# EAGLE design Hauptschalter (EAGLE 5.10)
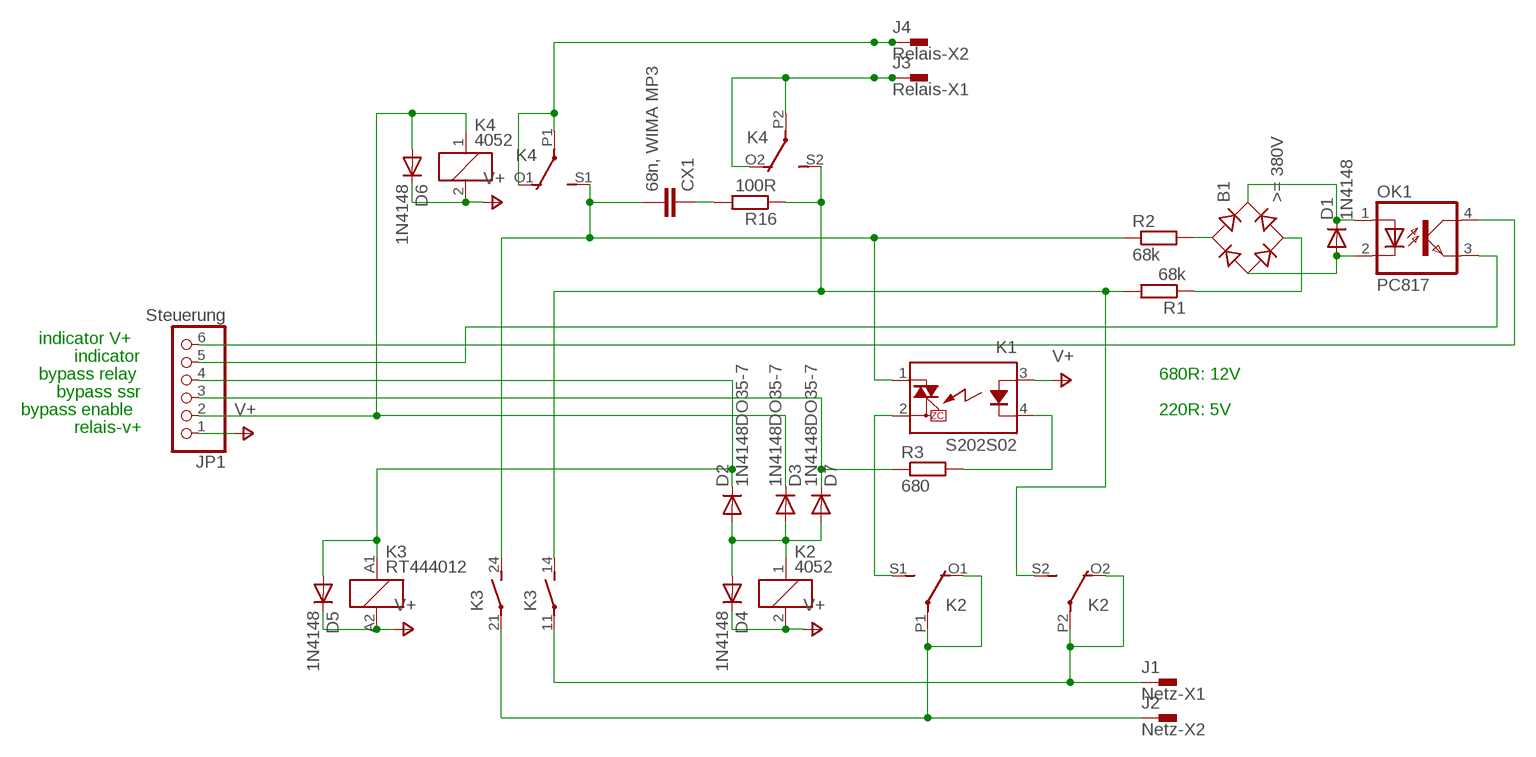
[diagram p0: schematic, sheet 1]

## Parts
B1  >= 380V  B-DIL  [B-DIL]
CX1  68n, WIMA MP3  CXXC15B8  [XC15B8]
D1  1N4148  DIODE-MINIMELF  [MINIMELF]
D2  1N4148DO35-7  [DO35-7]
D3  1N4148DO35-7  [DO35-7]
D4  1N4148  DIODE-MINIMELF  [MINIMELF]
D5  1N4148  DIODE-MINIMELF  [MINIMELF]
D6  1N4148  DIODE-MINIMELF  [MINIMELF]
D7  1N4148DO35-7  [DO35-7]
J1  Netz-X1  PIN2F061.080  [F061.080]
J2  Netz-X2  PIN2F061.080  [F061.080]
J3  Relais-X1  PIN2F061.080  [F061.080]
J4  Relais-X2  PIN2F061.080  [F061.080]
JP1  Steuerung  PINHD-1X6  [1X06]
K1  S202S02  [S202S02]
K2  4052  [F4052]
K3  RT444012  [RT2N/O]
K4  4052  [F4052]
OK1  PC817  [DIL04]
R1  68k  R-EU_0414/5V  [0414V]
R2  68k  R-EU_0414/15  [0414/15]
R3  680  R-EU_0207/10  [0207/10]
R16  100R  R-EU_0414/5V  [0414V]

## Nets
N$1: B1.AC1 R2.2
N$2: K1.4(K) R3.2
N$3: K2.S2(3:S) K3.14(2:S) K4.S2(3:S) R1.2 R16.1
N$4: B1.- D1.A OK1.2(C)
N$5: B1.+ D1.C OK1.1(A)
N$6: CX1.2 K1.1(DS1) K3.24(3:S) K4.S1(2:S) R2.1
N$7: D3.C D6.A JP1.2 K4.1
N$8: K1.2(DS2) K2.S1(2:S)
N$9: D2.C D5.A JP1.4 K3.A1
N$10: B1.AC2 R1.1
N$11: D2.A D3.A D4.A D7.A K2.1
N$12: J2.1A J2.1B(1.1) K2.O1(2:O) K2.P1(2:P) K3.21(3:P)
N$13: J1.1A J1.1B(1.1) K2.O2(3:O) K2.P2(3:P) K3.11(2:P)
N$14: J4.1A J4.1B(1.1) K4.O1(2:O) K4.P1(2:P)
N$15: J3.1A J3.1B(1.1) K4.O2(3:O) K4.P2(3:P)
N$16: JP1.6 OK1.4(COL)
N$17: JP1.5 OK1.3(EMIT)
N$18: D7.C JP1.3 R3.1
N$28: CX1.1 R16.2
V+: D4.C D5.C D6.C JP1.1 K1.3(A) K2.2 K3.A2 K4.2

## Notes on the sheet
- indicator V+
- indicator
- bypass relay | 680R: 12V
- bypass ssr
- bypass enable | 220R: 5V
- relais-v+

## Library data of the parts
B1 = rectifier:B-DIL: RECTIFIER
CX1 = rcl:CX: X CAPACITOR
D1 D4-D6 = diode:DIODE-: DIODE
D2 D3 D7 = diode:1N4148: DIODE
J1-J4 = con-faston:PIN2: Flachstecker Typ Tyco/Electronics/AMP TAB, FASTON
JP1 = pinhead:PINHD-1X6: PIN HEADER
K1 = relay:S*02S02: IT(rms) 8A, Zero Cross type SIP 4pin Triac output SSR Source: http://sharp-world.com/products/device/lineup/data/pdf/datasheet/s102s02_e.pdf
K2 K4 = relay:4052: RELAY 2 x switch, Finder
K3 = relay:RT44?*: Power PCB Relay SCHRACK 2 pole 8 A, DC and AC-coil Source: http://www.schrack.com/.. 5842.pdf
OK1 = optocoupler:PC817: SHARP OPTO COUPLER
R1-R3 R16 = rcl:R-EU_: RESISTOR, European symbol

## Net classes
1 mains: width 4 mm, clearance 2 mm

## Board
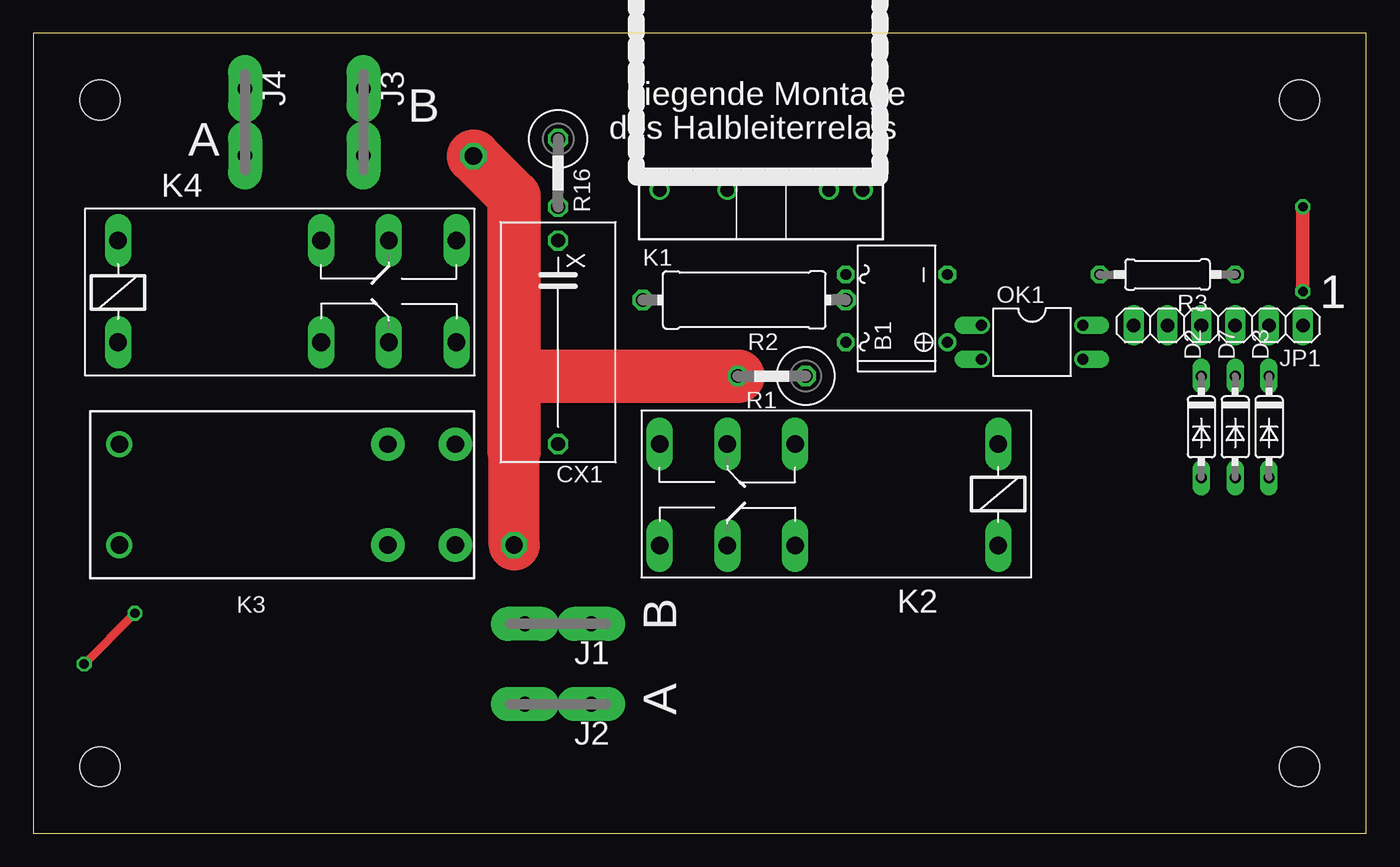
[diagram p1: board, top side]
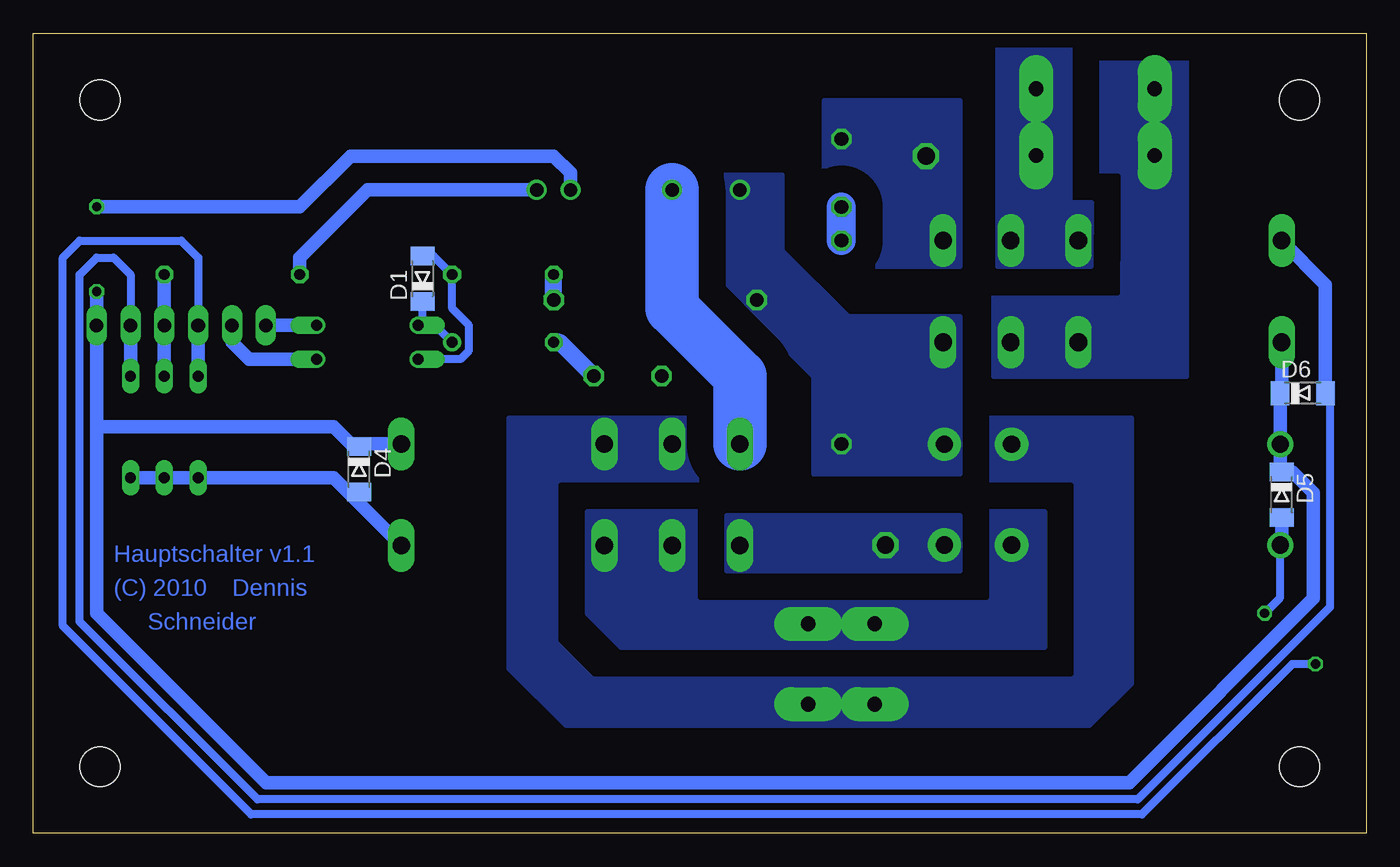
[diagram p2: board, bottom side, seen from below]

Size 100 x 60 mm. Coordinates in mm from the lower left corner, seen from the top.
Outline: 0,0 100,0 100,60 0,60 0,0
Copper layers (1*16): Top 0.035mm / dielectric 1.5mm / Bottom 0.035mm
Design rules "default *": minimum track width 10mil, minimum drill 24mil, track to track 8mil, track to pad 8mil, pad to pad 8mil, via to via 8mil, smd to smd 8mil, copper to edge 40mil, drill to drill 8mil, minimum pad ring 10mil, minimum via ring 8mil, stop-mask expansion 4mil, vias tented up to drill 0mil, thermal gap 10mil
Holes 3 mm at 5,55 5,5 95,55 95,5

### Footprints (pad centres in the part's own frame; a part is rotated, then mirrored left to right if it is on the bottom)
B-DIL = drill 0.813 round: + -2.54,-3.81 | drill 0.813 octagon: - 2.54,-3.81; AC1 2.54,3.81; AC2 -2.54,3.81
XC15B8 = drill 1.016 octagon: 1 -7.62,0; 2 7.62,0
MINIMELF = smd 1.4 x 1.8: A 1.7,0; C -1.7,0
DO35-7 = drill 0.813 long: A 3.81,0; C -3.81,0
F061.080 = drill 1.1 pad 2.54 long: 1A -2.5,0; 1B 2.5,0
1X06 = drill 1.016 long: 1 -6.35,0; 2 -3.81,0; 3 -1.27,0; 4 1.27,0; 5 3.81,0; 6 6.35,0
S202S02 = drill 1 round: 1 -7.62,0; 2 -2.54,0; 3 5.08,0; 4 7.62,0
F4052 = drill 1.321 long: 1 -3.81,3.81; 2 -3.81,-3.81; O1 11.43,-3.81; O2 11.43,3.81; P1 16.51,-3.81; P2 16.51,3.81; S1 21.59,-3.81; S2 21.59,3.81
RT2N/O = drill 1.3 pad 2.5 round: 11 7.56,-3.78; 14 12.6,-3.78; 21 7.56,3.78; 24 12.6,3.78 | drill 1.3 round: A1 -12.6,-3.78; A2 -12.6,3.78
DIL04 = drill 0.813 offset: 1 -1.27,-3.81; 2 1.27,-3.81; 3 1.27,3.81; 4 -1.27,3.81
0414V = drill 1.016 octagon: 1 -2.54,0; 2 2.54,0
0414/15 = drill 1.016 octagon: 1 -7.62,0; 2 7.62,0
0207/10 = drill 0.813 octagon: 1 -5.08,0; 2 5.08,0

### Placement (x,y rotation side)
B1  64.77,39.37 90 top
CX1  39.37,36.83 270 top
D1  70.8,41.59 90 bottom
D2  87.63,30.48 270 top
D3  92.71,30.48 270 top
D4  75.57,27.31 270 bottom
D5  6.35,25.4 270 bottom
D6  4.76,33.02 0 bottom
D7  90.17,30.48 270 top
J1  39.37,15.72 180 top
J2  39.37,9.68 180 top
J3  24.77,53.34 270 top
J4  15.88,53.34 270 top
JP1  88.9,38.1 180 top
K1  54.61,48.26 0 top
K2  68.58,25.4 180 top
K3  19.05,25.4 0 top
K4  10.16,40.64 0 top
OK1  74.93,36.83 270 top
R1  55.4,34.29 180 top
R2  53.34,40.01 0 top
R3  85.09,41.91 180 top
R16  39.37,49.53 270 top

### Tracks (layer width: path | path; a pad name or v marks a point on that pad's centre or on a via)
N$1
  Bottom 1.27: R2.2 B1.AC1
N$2
  Bottom 1.016: R3.2 80.01,43.18 74.93,48.26 K1.4
N$3  (via drill 1.3)
  Top 3.81: v36.07,21.62 36.07,28.7
  Top 4: v33.02,50.8 36.07,47.75 36.07,34.13 | 36.07,28.7 36.07,34.13 | 36.07,34.13 36.23,34.29 R1.2
  pour Bottom (isolate 2, rank 3, no thermals): 30.48,42.55 40.64,42.55 40.64,54.93 30.48,54.93
  pour Bottom (isolate 2, no thermals): 30.48,19.68 30.48,23.81 47.94,23.81 47.94,19.68
N$4
  Bottom 0.61: OK1.2 67.94,35.56 67.31,36.2 67.31,38.1 68.58,39.37 B1.- 69.96,43.29 D1.A
N$5
  Bottom 0.61: B1.+ 69.85,38.1 OK1.1 70.8,38.42 D1.C
N$6
  pour Bottom (isolate 2, no thermals): 30.48,26.99 30.48,38.73 38.89,38.73 43.81,43.66 43.81,49.37 48.74,49.37 48.74,41.59 41.43,34.29 41.43,26.99
N$7
  Bottom 0.61: JP1.2 92.71,41.91 93.98,43.18 95.25,43.18 96.52,41.91 96.52,15.88 83.19,2.54 17.14,2.54 2.7,16.99 2.7,32.66 D6.A | D6.A
  Bottom 1.016: K4.1 3.06,41.16 D6.A | JP1.2 D3.C
N$8
  Bottom 4: K2.S1 46.99,34.29 52.07,39.37 K1.2
N$9  (via drill 0.7)
  Top 0.61: v3.81,12.7 v7.62,16.51
  Bottom 0.61: v3.81,12.7 5.56,12.7 16.83,1.43 83.66,1.43 97.79,15.56 97.79,43.18 96.52,44.45 88.9,44.45 87.63,43.18 JP1.4 | v7.62,16.51 6.45,17.68 K3.A1
  Bottom 1.016: D5.A 6.35,21.72 K3.A1 | JP1.4 D2.C
N$10
  Bottom 1.27: R1.1 60.48,36.83 B1.AC2
N$11
  Bottom 1.016: D3.A D7.A D2.A 77.47,26.67 76.41,25.61 | 75.77,25.4 D4.A 76.41,25.61 | K2.1 76.41,25.61
N$12
  pour Bottom (isolate 2, rank 4, no thermals): 17.62,11.27 20.8,8.1 60.01,8.1 64.29,12.38 64.29,31.11 17.62,31.11
N$13
  pour Bottom (isolate 2, rank 2, no thermals): 24.13,24.13 24.13,13.97 55.88,13.97 58.42,16.51 58.42,24.13
N$14
  pour Bottom (isolate 2, rank 2, no thermals): 13.49,58.74 13.49,34.29 27.94,34.29 27.94,58.74
N$15
  pour Bottom (no thermals): 22.23,59.21 22.23,47.31 20.64,47.31 20.64,42.55 27.62,42.55 27.62,47.31 27.62,47.31 27.62,59.21
N$16
  Bottom 1.016: OK1.4 JP1.6
N$17
  Bottom 1.016: OK1.3 83.82,35.56 85.09,36.83 JP1.5
N$18
  Bottom 1.016: R3.1 JP1.3 D7.C
N$28
  Bottom 2.184: CX1.1 R16.2
V+  (via drill 0.7)
  Top 1.016: v95.25,40.64 v95.25,46.99
  Bottom 1.016: 95.25,30.48 77.47,30.48 76.2,29.21 | 95.25,30.48 95.25,16.51 82.55,3.81 17.78,3.81 3.97,17.62 3.97,25.56 5.51,27.1 D5.C 6.45,27.2 K3.A2 6.46,29.19 D6.C 6.35,33.13 K4.2 | 76.2,29.21 K2.2 | 95.25,30.48 JP1.1 v95.25,40.64 | D4.C 76,29 76.2,29.21 | K1.3 59.69,49.53 60.96,50.8 76.2,50.8 80.01,46.99 v95.25,46.99

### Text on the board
Bottom: Hauptschalter v1.1 | Dennis | (C) 2010 | Schneider
tPlace: Liegende Montage | des Halbleiterrelais
tNames: B | A | 1 | B | A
